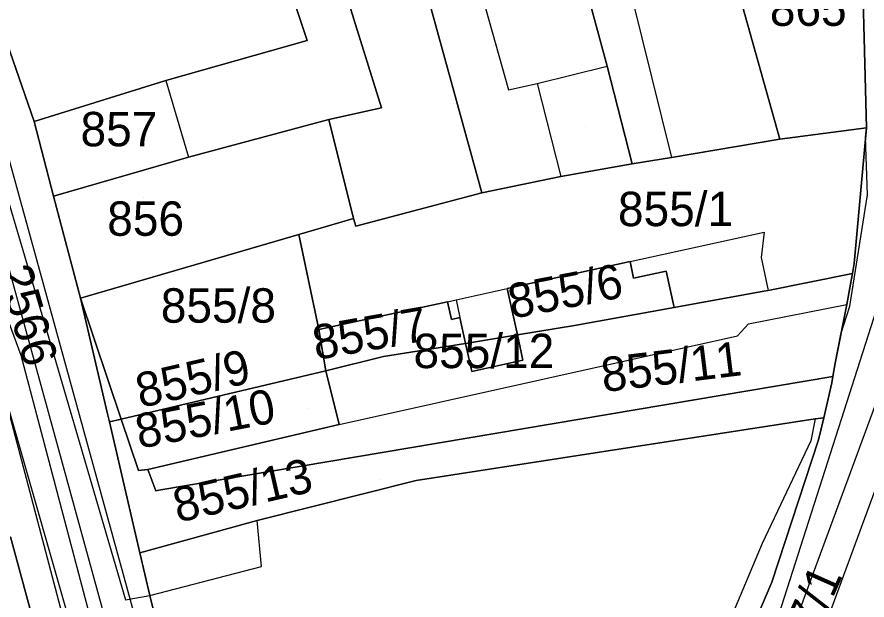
# Model space of a CAD drawing. Extents: x -263423 to -261326, y -1240067 to -1237864.
# Drawn here: x -262632.6 to -262583.21, y -1239608.29 to -1239574.42 of the extents above; entities that cross this region are included whole.
import ezdxf

# ---------------------------------------------------------------- set-up
doc = ezdxf.new("R2010")
doc.units = 0
for name, color, linetype in [('body_kn', 7, 'Continuous'), ('kladpar_druhypozemkov', 7, 'Continuous'), ('kladpar_hranice', 7, 'Continuous'), ('kladpar_parcelnecisla', 7, 'Continuous'), ('kladpar_plochy', 7, 'Continuous'), ('kladpar_sipky', 7, 'Continuous'), ('tarchy_linie', 7, 'Continuous'), ('zappar_hrandruhpozemk', 7, 'Continuous')]:
    doc.layers.add(name, color=color, linetype=linetype)

msp = doc.modelspace()

# ---------------------------------------------------------------- linework, layer by layer
at = {"layer": 'body_kn'}
for p, q in [((-262615.74, -1239575.79), (-262615.74, -1239575.79)), ((-262598.31, -1239577.27), (-262598.31, -1239577.27)), ((-262623.96, -1239578.11), (-262623.96, -1239578.11)), ((-262623.96, -1239578.11), (-262623.96, -1239578.11)), ((-262602.38, -1239578.27), (-262602.38, -1239578.27)), ((-262602.38, -1239578.27), (-262602.38, -1239578.27)), ((-262604.04, -1239578.65), (-262604.04, -1239578.65)), ((-262611.43, -1239579.7), (-262611.43, -1239579.7)), ((-262631.61, -1239580.49), (-262631.61, -1239580.49)), ((-262614.48, -1239580.38), (-262614.48, -1239580.38)), ((-262583.24, -1239580.85), (-262583.24, -1239580.85)), ((-262588.27, -1239581.52), (-262588.27, -1239581.52)), ((-262583.29, -1239581.4), (-262583.29, -1239581.4)), ((-262622.64, -1239582.57), (-262622.64, -1239582.57)), ((-262622.64, -1239582.57), (-262622.64, -1239582.57)), ((-262594.57, -1239582.58), (-262594.57, -1239582.58)), ((-262596.86, -1239582.95), (-262596.86, -1239582.95)), ((-262601, -1239583.69), (-262601, -1239583.69)), ((-262605.59, -1239584.63), (-262605.59, -1239584.63)), ((-262630.48, -1239584.83), (-262630.48, -1239584.83)), ((-262613.04, -1239586.12), (-262613.04, -1239586.12)), ((-262612.91, -1239586.57), (-262612.91, -1239586.57)), ((-262616.23, -1239587.06), (-262616.23, -1239587.06)), ((-262616.23, -1239587.06), (-262616.23, -1239587.06)), ((-262589.18, -1239586.92), (-262589.18, -1239586.92)), ((-262596.98, -1239588.62), (-262596.98, -1239588.62)), ((-262596.98, -1239588.62), (-262596.98, -1239588.62)), ((-262589.35, -1239588.39), (-262589.35, -1239588.39)), ((-262594.87, -1239589.19), (-262594.87, -1239589.19)), ((-262583.96, -1239588.74), (-262583.96, -1239588.74)), ((-262596.77, -1239589.6), (-262596.77, -1239589.6)), ((-262584.06, -1239589.32), (-262584.06, -1239589.32)), ((-262604.12, -1239590.2), (-262604.12, -1239590.2)), ((-262604.12, -1239590.2), (-262604.12, -1239590.2)), ((-262584.16, -1239589.95), (-262584.16, -1239589.95)), ((-262589.21, -1239590.35), (-262589.21, -1239590.35)), ((-262588.96, -1239590.3), (-262588.96, -1239590.3)), ((-262628.91, -1239590.76), (-262628.91, -1239590.76)), ((-262628.91, -1239590.76), (-262628.91, -1239590.76)), ((-262607.58, -1239590.97), (-262607.58, -1239590.97)), ((-262607.58, -1239590.97), (-262607.58, -1239590.97)), ((-262607.09, -1239590.86), (-262607.09, -1239590.86)), ((-262607.09, -1239590.86), (-262607.09, -1239590.86)), ((-262584.39, -1239591.12), (-262584.39, -1239591.12)), ((-262594.42, -1239591.3), (-262594.42, -1239591.3)), ((-262584.21, -1239591.22), (-262584.21, -1239591.22)), ((-262607.35, -1239591.99), (-262607.35, -1239591.99)), ((-262606.87, -1239591.88), (-262606.87, -1239591.88)), ((-262615.06, -1239592.57), (-262615.06, -1239592.57)), ((-262615.06, -1239592.57), (-262615.06, -1239592.57)), ((-262600.21, -1239592.35), (-262600.21, -1239592.35)), ((-262590.09, -1239592.25), (-262590.09, -1239592.25)), ((-262603.52, -1239592.89), (-262603.52, -1239592.89)), ((-262603.52, -1239592.89), (-262603.52, -1239592.89)), ((-262590.73, -1239592.95), (-262590.73, -1239592.95)), ((-262584.73, -1239592.85), (-262584.73, -1239592.85)), ((-262606.54, -1239593.38), (-262606.54, -1239593.38)), ((-262606.54, -1239593.38), (-262606.54, -1239593.38)), ((-262632.35, -1239594.09), (-262632.35, -1239594.09)), ((-262630.45, -1239594.13), (-262630.45, -1239594.13)), ((-262611.31, -1239594.15), (-262611.31, -1239594.15)), ((-262603.2, -1239594.35), (-262603.2, -1239594.35)), ((-262585.06, -1239594.53), (-262585.06, -1239594.53)), ((-262614.65, -1239594.98), (-262614.65, -1239594.98)), ((-262606.17, -1239595.01), (-262606.17, -1239595.01)), ((-262585.19, -1239595.3), (-262585.19, -1239595.3)), ((-262585.26, -1239595.68), (-262585.26, -1239595.68)), ((-262627.34, -1239597.48), (-262627.34, -1239597.48)), ((-262627.23, -1239597.94), (-262627.23, -1239597.94)), ((-262626.55, -1239597.78), (-262626.55, -1239597.78)), ((-262626.55, -1239597.78), (-262626.55, -1239597.78)), ((-262613.88, -1239598.09), (-262613.88, -1239598.09)), ((-262613.88, -1239598.09), (-262613.88, -1239598.09)), ((-262586.22, -1239597.77), (-262586.22, -1239597.77)), ((-262586.22, -1239597.77), (-262586.22, -1239597.77)), ((-262585.71, -1239597.71), (-262585.71, -1239597.71)), ((-262586.48, -1239599.04), (-262586.48, -1239599.04)), ((-262586.03, -1239598.98), (-262586.03, -1239598.98)), ((-262625.54, -1239600.77), (-262625.54, -1239600.77)), ((-262625, -1239600.71), (-262625, -1239600.71)), ((-262625, -1239600.71), (-262625, -1239600.71)), ((-262609.4, -1239601.36), (-262609.4, -1239601.36)), ((-262624.54, -1239601.95), (-262624.54, -1239601.95)), ((-262624.36, -1239601.92), (-262624.36, -1239601.92)), ((-262625.96, -1239603.38), (-262625.96, -1239603.38)), ((-262618.64, -1239603.67), (-262618.64, -1239603.67)), ((-262589.3, -1239605.02), (-262589.3, -1239605.02)), ((-262625.46, -1239605.55), (-262625.46, -1239605.55)), ((-262618.39, -1239606.35), (-262618.39, -1239606.35)), ((-262588.74, -1239607.25), (-262588.74, -1239607.25)), ((-262626.29, -1239608.28), (-262626.29, -1239608.28)), ((-262624.89, -1239608.03), (-262624.89, -1239608.03)), ((-262624.89, -1239608.03), (-262624.89, -1239608.03))]:
    msp.add_line(p, q, dxfattribs=at)
at = {"layer": 'kladpar_druhypozemkov'}
for p, q in [((-262626.77, -1239580.03), (-262626.77, -1239580.03)), ((-262599.58, -1239580.77), (-262599.58, -1239580.77)), ((-262593.7, -1239584.71), (-262593.7, -1239584.71)), ((-262625.27, -1239584.93), (-262625.27, -1239584.93)), ((-262599.49, -1239589.74), (-262599.49, -1239589.74)), ((-262620.55, -1239590.47), (-262620.55, -1239590.47)), ((-262610.47, -1239592.31), (-262610.47, -1239592.31)), ((-262604.76, -1239593.38), (-262604.76, -1239593.38)), ((-262594.51, -1239593.43), (-262594.51, -1239593.43)), ((-262627.49, -1239595.55), (-262627.49, -1239595.55)), ((-262615.73, -1239597.14), (-262615.73, -1239597.14)), ((-262631.77, -1239599.33), (-262631.77, -1239599.33)), ((-262611.5, -1239601.28), (-262611.5, -1239601.28)), ((-262584.67, -1239602.93), (-262584.67, -1239602.93))]:
    msp.add_line(p, q, dxfattribs=at)
at = {"layer": 'kladpar_hranice'}
for p, q in [((-262606.54, -1239593.38), (-262603.52, -1239592.89)), ((-262603.52, -1239592.89), (-262606.54, -1239593.38))]:
    msp.add_line(p, q, dxfattribs=at)
for points in [[(-262607.74, -1239542.52), (-262606.71, -1239546.31), (-262602.21, -1239562.89), (-262598.31, -1239577.27), (-262596.86, -1239582.95), (-262601, -1239583.69), (-262605.59, -1239584.63), (-262611.37, -1239563.65), (-262611.05, -1239563.52), (-262616.08, -1239544.9), (-262621.75, -1239525.07), (-262619.2, -1239524.45), (-262614.36, -1239523.39), (-262607.74, -1239542.52)], [(-262616.08, -1239544.9), (-262611.05, -1239563.52), (-262611.37, -1239563.65), (-262605.59, -1239584.63), (-262612.91, -1239586.57), (-262613.04, -1239586.12), (-262614.48, -1239580.38), (-262611.43, -1239579.7), (-262616.15, -1239564.52), (-262620.67, -1239546.73), (-262623.98, -1239547.54), (-262629.58, -1239527.39), (-262621.75, -1239525.07), (-262616.08, -1239544.9)], [(-262623.96, -1239578.11), (-262615.74, -1239575.79), (-262619.65, -1239563.99), (-262620.34, -1239560.87), (-262622.73, -1239552.32), (-262623.98, -1239547.54), (-262620.67, -1239546.73), (-262616.15, -1239564.52), (-262611.43, -1239579.7), (-262614.48, -1239580.38), (-262622.64, -1239582.57), (-262630.48, -1239584.83), (-262631.61, -1239580.49), (-262623.96, -1239578.11)], [(-262627.47, -1239562.43), (-262627.35, -1239562.81), (-262620.34, -1239560.87), (-262619.65, -1239563.99), (-262615.74, -1239575.79), (-262623.96, -1239578.11), (-262631.61, -1239580.49), (-262636.9, -1239565.18), (-262627.47, -1239562.43)], [(-262602.21, -1239562.89), (-262599.62, -1239562.19), (-262598.8, -1239561.99), (-262598, -1239561.8), (-262594.11, -1239560.74), (-262591.72, -1239569.22), (-262588.27, -1239581.52), (-262594.57, -1239582.58), (-262596.86, -1239582.95), (-262598.31, -1239577.27), (-262602.21, -1239562.89)], [(-262636.9, -1239565.18), (-262631.61, -1239580.49), (-262630.48, -1239584.83), (-262628.91, -1239590.76)], [(-262615.43, -1239658.85), (-262611.8, -1239653.42), (-262602.6, -1239639.66), (-262599.2, -1239631.4), (-262592.2, -1239614.87), (-262590.53, -1239610.81), (-262589.57, -1239609.22), (-262588.74, -1239607.25), (-262586.03, -1239598.98), (-262585.71, -1239597.71), (-262585.26, -1239595.68), (-262585.19, -1239595.3), (-262585.06, -1239594.53), (-262584.39, -1239591.12), (-262584.16, -1239589.95), (-262584.06, -1239589.32), (-262583.96, -1239588.74), (-262583.24, -1239580.85), (-262583.57, -1239568.17)], [(-262583.57, -1239568.17), (-262583.24, -1239580.85), (-262588.27, -1239581.52), (-262591.72, -1239569.22), (-262583.57, -1239568.17)], [(-262622.64, -1239582.57), (-262614.48, -1239580.38), (-262613.04, -1239586.12), (-262616.23, -1239587.06), (-262628.91, -1239590.76), (-262630.48, -1239584.83), (-262622.64, -1239582.57)], [(-262616.23, -1239587.06), (-262613.04, -1239586.12), (-262612.91, -1239586.57), (-262605.59, -1239584.63), (-262601, -1239583.69), (-262596.86, -1239582.95), (-262594.57, -1239582.58), (-262588.27, -1239581.52), (-262583.24, -1239580.85), (-262583.96, -1239588.74), (-262584.06, -1239589.32), (-262588.96, -1239590.3), (-262589.21, -1239590.35), (-262594.42, -1239591.3), (-262594.87, -1239589.19), (-262596.77, -1239589.6), (-262596.98, -1239588.62), (-262604.12, -1239590.2), (-262603.52, -1239592.89)], [(-262628.91, -1239590.76), (-262616.23, -1239587.06), (-262615.06, -1239592.57), (-262614.65, -1239594.98), (-262626.55, -1239597.78), (-262628.91, -1239590.76)], [(-262606.54, -1239593.38), (-262606.87, -1239591.88), (-262607.35, -1239591.99), (-262607.58, -1239590.97), (-262615.06, -1239592.57), (-262616.23, -1239587.06)], [(-262604.12, -1239590.2), (-262596.98, -1239588.62), (-262596.77, -1239589.6), (-262594.87, -1239589.19), (-262594.42, -1239591.3), (-262600.21, -1239592.35), (-262603.52, -1239592.89), (-262604.12, -1239590.2)], [(-262625, -1239600.71), (-262613.88, -1239598.09), (-262614.65, -1239594.98), (-262611.31, -1239594.15), (-262606.54, -1239593.38), (-262606.17, -1239595.01), (-262603.2, -1239594.35), (-262603.52, -1239592.89), (-262600.21, -1239592.35), (-262594.42, -1239591.3), (-262589.21, -1239590.35), (-262588.96, -1239590.3), (-262584.06, -1239589.32), (-262584.16, -1239589.95), (-262584.39, -1239591.12), (-262585.06, -1239594.53), (-262585.19, -1239595.3), (-262624.36, -1239601.92), (-262624.54, -1239601.95), (-262625, -1239600.71)], [(-262628.91, -1239590.76), (-262627.34, -1239597.48), (-262627.23, -1239597.94), (-262625.96, -1239603.38), (-262625.46, -1239605.55), (-262624.89, -1239608.03), (-262621.82, -1239620.4), (-262619.3, -1239628.89), (-262615.66, -1239642.02), (-262614.65, -1239641.84), (-262602.6, -1239639.66), (-262611.8, -1239653.42), (-262615.43, -1239658.85), (-262621.03, -1239667.22), (-262620.64, -1239664.23), (-262619.59, -1239654.74), (-262619.71, -1239653.28), (-262620.02, -1239651.81), (-262622.09, -1239644.48), (-262623.16, -1239640.4), (-262625.74, -1239631.34), (-262632.97, -1239604.62)], [(-262628.91, -1239590.76), (-262626.55, -1239597.78), (-262627.23, -1239597.94), (-262627.34, -1239597.48), (-262628.91, -1239590.76)], [(-262615.06, -1239592.57), (-262607.58, -1239590.97), (-262607.35, -1239591.99), (-262606.87, -1239591.88), (-262606.54, -1239593.38), (-262611.31, -1239594.15), (-262614.65, -1239594.98), (-262615.06, -1239592.57)], [(-262603.52, -1239592.89), (-262603.2, -1239594.35), (-262606.17, -1239595.01), (-262606.54, -1239593.38)], [(-262626.55, -1239597.78), (-262614.65, -1239594.98), (-262613.88, -1239598.09), (-262625, -1239600.71), (-262625.54, -1239600.77), (-262626.55, -1239597.78)], [(-262626.55, -1239597.78), (-262625.54, -1239600.77), (-262625, -1239600.71), (-262624.54, -1239601.95), (-262624.36, -1239601.92), (-262585.19, -1239595.3), (-262585.26, -1239595.68), (-262585.71, -1239597.71), (-262586.22, -1239597.77), (-262609.4, -1239601.36), (-262618.64, -1239603.67), (-262625.46, -1239605.55), (-262625.96, -1239603.38), (-262627.23, -1239597.94), (-262626.55, -1239597.78)], [(-262586.22, -1239597.77), (-262585.71, -1239597.71), (-262586.03, -1239598.98), (-262588.74, -1239607.25), (-262589.57, -1239609.22), (-262590.53, -1239610.81), (-262592.2, -1239614.87), (-262599.2, -1239631.4), (-262602.6, -1239639.66), (-262614.65, -1239641.84), (-262615.66, -1239642.02), (-262619.3, -1239628.89), (-262621.82, -1239620.4), (-262624.89, -1239608.03), (-262625.46, -1239605.55), (-262618.64, -1239603.67), (-262609.4, -1239601.36), (-262586.22, -1239597.77)], [(-262632.97, -1239604.62), (-262625.74, -1239631.34), (-262692.34, -1239650.83)]]:
    msp.add_lwpolyline(points, dxfattribs=at)
at = {"layer": 'kladpar_plochy'}
for points in [[(-262607.74, -1239542.52), (-262606.71, -1239546.31), (-262602.21, -1239562.89), (-262598.31, -1239577.27), (-262596.86, -1239582.95), (-262601, -1239583.69), (-262605.59, -1239584.63), (-262611.37, -1239563.65), (-262611.05, -1239563.52), (-262616.08, -1239544.9), (-262621.75, -1239525.07), (-262619.2, -1239524.45), (-262614.36, -1239523.39)], [(-262616.08, -1239544.9), (-262611.05, -1239563.52), (-262611.37, -1239563.65), (-262605.59, -1239584.63), (-262612.91, -1239586.57), (-262613.04, -1239586.12), (-262614.48, -1239580.38), (-262611.43, -1239579.7), (-262616.15, -1239564.52), (-262620.67, -1239546.73), (-262623.98, -1239547.54), (-262629.58, -1239527.39), (-262621.75, -1239525.07)], [(-262623.96, -1239578.11), (-262615.74, -1239575.79), (-262619.65, -1239563.99), (-262620.34, -1239560.87), (-262622.73, -1239552.32), (-262623.98, -1239547.54), (-262620.67, -1239546.73), (-262616.15, -1239564.52), (-262611.43, -1239579.7), (-262614.48, -1239580.38), (-262622.64, -1239582.57), (-262630.48, -1239584.83), (-262631.61, -1239580.49)], [(-262627.47, -1239562.43), (-262627.35, -1239562.81), (-262620.34, -1239560.87), (-262619.65, -1239563.99), (-262615.74, -1239575.79), (-262623.96, -1239578.11), (-262631.61, -1239580.49), (-262636.9, -1239565.18)], [(-262602.21, -1239562.89), (-262599.62, -1239562.19), (-262598.8, -1239561.99), (-262598, -1239561.8), (-262594.11, -1239560.74), (-262591.72, -1239569.22), (-262588.27, -1239581.52), (-262594.57, -1239582.58), (-262596.86, -1239582.95), (-262598.31, -1239577.27)], [(-262583.57, -1239568.17), (-262583.24, -1239580.85), (-262588.27, -1239581.52), (-262591.72, -1239569.22)], [(-262622.64, -1239582.57), (-262614.48, -1239580.38), (-262613.04, -1239586.12), (-262616.23, -1239587.06), (-262628.91, -1239590.76), (-262630.48, -1239584.83)], [(-262616.23, -1239587.06), (-262613.04, -1239586.12), (-262612.91, -1239586.57), (-262605.59, -1239584.63), (-262601, -1239583.69), (-262596.86, -1239582.95), (-262594.57, -1239582.58), (-262588.27, -1239581.52), (-262583.24, -1239580.85), (-262583.96, -1239588.74), (-262584.06, -1239589.32), (-262588.96, -1239590.3), (-262589.21, -1239590.35), (-262594.42, -1239591.3), (-262594.87, -1239589.19), (-262596.77, -1239589.6), (-262596.98, -1239588.62), (-262604.12, -1239590.2), (-262603.52, -1239592.89), (-262606.54, -1239593.38), (-262606.87, -1239591.88), (-262607.35, -1239591.99), (-262607.58, -1239590.97), (-262615.06, -1239592.57)], [(-262628.91, -1239590.76), (-262616.23, -1239587.06), (-262615.06, -1239592.57), (-262614.65, -1239594.98), (-262626.55, -1239597.78)], [(-262604.12, -1239590.2), (-262596.98, -1239588.62), (-262596.77, -1239589.6), (-262594.87, -1239589.19), (-262594.42, -1239591.3), (-262600.21, -1239592.35), (-262603.52, -1239592.89)], [(-262625, -1239600.71), (-262613.88, -1239598.09), (-262614.65, -1239594.98), (-262611.31, -1239594.15), (-262606.54, -1239593.38), (-262606.17, -1239595.01), (-262603.2, -1239594.35), (-262603.52, -1239592.89), (-262600.21, -1239592.35), (-262594.42, -1239591.3), (-262589.21, -1239590.35), (-262588.96, -1239590.3), (-262584.06, -1239589.32), (-262584.16, -1239589.95), (-262584.39, -1239591.12), (-262585.06, -1239594.53), (-262585.19, -1239595.3), (-262624.36, -1239601.92), (-262624.54, -1239601.95)], [(-262628.91, -1239590.76), (-262626.55, -1239597.78), (-262627.23, -1239597.94), (-262627.34, -1239597.48)], [(-262615.06, -1239592.57), (-262607.58, -1239590.97), (-262607.35, -1239591.99), (-262606.87, -1239591.88), (-262606.54, -1239593.38), (-262611.31, -1239594.15), (-262614.65, -1239594.98)], [(-262606.54, -1239593.38), (-262603.52, -1239592.89), (-262603.2, -1239594.35), (-262606.17, -1239595.01)], [(-262626.55, -1239597.78), (-262614.65, -1239594.98), (-262613.88, -1239598.09), (-262625, -1239600.71), (-262625.54, -1239600.77)], [(-262626.55, -1239597.78), (-262625.54, -1239600.77), (-262625, -1239600.71), (-262624.54, -1239601.95), (-262624.36, -1239601.92), (-262585.19, -1239595.3), (-262585.26, -1239595.68), (-262585.71, -1239597.71), (-262586.22, -1239597.77), (-262609.4, -1239601.36), (-262618.64, -1239603.67), (-262625.46, -1239605.55), (-262625.96, -1239603.38), (-262627.23, -1239597.94)], [(-262586.22, -1239597.77), (-262585.71, -1239597.71), (-262586.03, -1239598.98), (-262588.74, -1239607.25), (-262589.57, -1239609.22), (-262590.53, -1239610.81), (-262592.2, -1239614.87), (-262599.2, -1239631.4), (-262602.6, -1239639.66), (-262614.65, -1239641.84), (-262615.66, -1239642.02), (-262619.3, -1239628.89), (-262621.82, -1239620.4), (-262624.89, -1239608.03), (-262625.46, -1239605.55), (-262618.64, -1239603.67), (-262609.4, -1239601.36)]]:
    msp.add_lwpolyline(points, close=True, dxfattribs=at)
for points in [[(-262636.9, -1239565.18), (-262631.61, -1239580.49), (-262630.48, -1239584.83), (-262628.91, -1239590.76), (-262627.34, -1239597.48), (-262627.23, -1239597.94), (-262625.96, -1239603.38), (-262625.46, -1239605.55), (-262624.89, -1239608.03), (-262621.82, -1239620.4)], [(-262622.98, -1239676.89), (-262621.03, -1239667.22), (-262615.43, -1239658.85), (-262611.8, -1239653.42), (-262602.6, -1239639.66), (-262599.2, -1239631.4), (-262592.2, -1239614.87), (-262590.53, -1239610.81), (-262589.57, -1239609.22), (-262588.74, -1239607.25), (-262586.03, -1239598.98), (-262585.71, -1239597.71), (-262585.26, -1239595.68), (-262585.19, -1239595.3), (-262585.06, -1239594.53), (-262584.39, -1239591.12), (-262584.16, -1239589.95), (-262584.06, -1239589.32), (-262583.96, -1239588.74), (-262583.24, -1239580.85), (-262583.57, -1239568.17)], [(-262632.97, -1239604.62), (-262625.74, -1239631.34), (-262692.34, -1239650.83)], [(-262625.74, -1239631.34), (-262632.97, -1239604.62)]]:
    msp.add_lwpolyline(points, dxfattribs=at)
at = {"layer": 'kladpar_sipky'}
msp.add_line((-262627.28, -1239596.79), (-262627.28, -1239596.79), dxfattribs=at)
at = {"layer": 'tarchy_linie'}
for points in [[(-262589.94, -1239510.37), (-262590.29, -1239520.22), (-262583.63, -1239553.12), (-262580.22, -1239590.13), (-262598.17, -1239638.84), (-262610.71, -1239664.55)], [(-262593.09, -1239511.41), (-262591.03, -1239517.52), (-262582.87, -1239564.2), (-262581.93, -1239575.53), (-262581.63, -1239584.7), (-262582.68, -1239591.46), (-262590.05, -1239614.5), (-262607.03, -1239655.6), (-262607.77, -1239657.08), (-262611.54, -1239661.47)], [(-262645.02, -1239533.84), (-262645.19, -1239537.35), (-262635.34, -1239574.27), (-262635.39, -1239574.28), (-262622.12, -1239622.51), (-262609.75, -1239668.08), (-262613.04, -1239668.97), (-262613.98, -1239665.48), (-262614.31, -1239666.45), (-262617.82, -1239665.28), (-262618.92, -1239663.07), (-262618.06, -1239658.77), (-262618.15, -1239653.99), (-262633.83, -1239594.56), (-262637.09, -1239585.76), (-262638.52, -1239582.28), (-262652.71, -1239533.43), (-262651.29, -1239533.03), (-262648.55, -1239532.26), (-262648.07, -1239532.13), (-262646.67, -1239531.74), (-262645.64, -1239531.45), (-262645.02, -1239533.84)], [(-262646.67, -1239531.74), (-262646.95, -1239537.54), (-262637.03, -1239574.72), (-262623.76, -1239622.96), (-262611.84, -1239666.88)], [(-262613.82, -1239664.98), (-262616.72, -1239664.01), (-262617.3, -1239662.85), (-262616.51, -1239658.91), (-262616.6, -1239653.78), (-262632.35, -1239594.09), (-262635.65, -1239585.2), (-262637.05, -1239581.77), (-262651, -1239533.75), (-262648.5, -1239532.5), (-262648.55, -1239532.26)], [(-262581.95, -1239552.87), (-262578.49, -1239590.36), (-262596.6, -1239639.51), (-262610.03, -1239667.05), (-262610.71, -1239664.55), (-262611.54, -1239661.47), (-262612.03, -1239659.66), (-262609.07, -1239656.22), (-262608.44, -1239654.96), (-262591.53, -1239614.03), (-262590.46, -1239610.69), (-262589.57, -1239609.22), (-262588.74, -1239607.25), (-262586.03, -1239598.98), (-262585.71, -1239597.71), (-262585.26, -1239595.68), (-262585.19, -1239595.3), (-262585.06, -1239594.53), (-262584.73, -1239592.85), (-262584.21, -1239591.22), (-262583.18, -1239584.75), (-262583.29, -1239581.4), (-262583.24, -1239580.85), (-262583.57, -1239568.17)]]:
    msp.add_lwpolyline(points, dxfattribs=at)
at = {"layer": 'zappar_hrandruhpozemk'}
for p, q in [((-262613.73, -1239544.34), (-262604.04, -1239578.65)), ((-262599.62, -1239562.19), (-262594.57, -1239582.58)), ((-262639.7, -1239562.81), (-262630.45, -1239594.13)), ((-262602.38, -1239578.27), (-262598.31, -1239577.27)), ((-262623.96, -1239578.11), (-262622.64, -1239582.57)), ((-262607.09, -1239590.86), (-262604.12, -1239590.2)), ((-262607.58, -1239590.97), (-262607.09, -1239590.86)), ((-262607.09, -1239590.86), (-262606.87, -1239591.88)), ((-262618.39, -1239606.35), (-262618.64, -1239603.67)), ((-262624.89, -1239608.03), (-262618.39, -1239606.35))]:
    msp.add_line(p, q, dxfattribs=at)
for points in [[(-262642.69, -1239563.63), (-262629.67, -1239609.16), (-262615.43, -1239658.85)], [(-262604.04, -1239578.65), (-262602.38, -1239578.27), (-262601, -1239583.69)], [(-262596.98, -1239588.62), (-262589.18, -1239586.92), (-262589.35, -1239588.39), (-262588.96, -1239590.3)], [(-262613.88, -1239598.09), (-262590.73, -1239592.95), (-262590.09, -1239592.25), (-262584.39, -1239591.12)], [(-262630.45, -1239594.13), (-262626.29, -1239608.28), (-262624.89, -1239608.03)], [(-262586.22, -1239597.77), (-262586.48, -1239599.04), (-262589.3, -1239605.02), (-262600.34, -1239631.27)]]:
    msp.add_lwpolyline(points, dxfattribs=at)

# ---------------------------------------------------------------- texts
at = {"layer": 'kladpar_parcelnecisla'}
for s, p in [('865', (-262588.856, -1239574.93)), ('857', (-262628.908, -1239581.93)), ('855/1', (-262597.681, -1239586.57)), ('856', (-262627.356, -1239587.13)), ('855/8', (-262624.244, -1239592.18)), ('855/12', (-262609.559, -1239594.82))]:
    msp.add_text(s, height=2, dxfattribs=at).set_placement(p)
for s, rotation, p in [('2566', 286, (-262633.748, -1239589.14)), ('855/6', 11, (-262603.843, -1239591.959)), ('855/7', 10, (-262615.227, -1239594.353)), ('855/11', 7, (-262598.53, -1239596.221)), ('855/9', 13, (-262625.429, -1239597.145)), ('855/10', 11, (-262625.498, -1239599.512)), ('855/13', 13, (-262623.26, -1239603.808)), ('2567/1', 66, (-262587.931, -1239614.35))]:
    msp.add_text(s, height=2, rotation=rotation, dxfattribs=at).set_placement(p)

doc.saveas('drawing.dxf')
